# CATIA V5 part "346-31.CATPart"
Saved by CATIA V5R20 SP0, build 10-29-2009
Part number: 346-31
Definition: NONE
Nomenclature: 346-31
Source: Unknown
Description: 346-31
Bounding box of the stored display mesh (mm): x 0 to 72, y -36 to 36, z -36 to 36
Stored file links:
  C:\Users\Utente\Desktop\IO LAVORO\3D X SITO CF\X SITO\3D files 346\346-31.CATPart
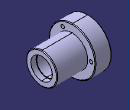
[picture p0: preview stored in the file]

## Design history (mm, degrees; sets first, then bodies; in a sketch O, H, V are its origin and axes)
Body1 "346-31" (main body)
  Solid1: solid without history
